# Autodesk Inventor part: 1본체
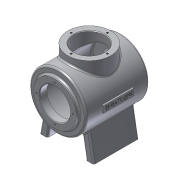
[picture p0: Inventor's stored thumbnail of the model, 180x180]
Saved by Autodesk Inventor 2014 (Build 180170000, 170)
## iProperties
Created: 2015-01
Part Number: 1본체
Material: 알루미늄 6061
Document SubType Name: Modeling
Designer: L-10
Density: 2.71 g/cm^3
Appearance: 알루미늄 - 평지
Mass: 953.119 g
Surface Area: 1057.99 cm^2
Volume: 351.704 cm^3
Author: L-10
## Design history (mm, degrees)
sketch "스케치1"
  geometry: C1 r 50 at (0, 0); 1 further point
  constraints: 1 centre point, 1 coincident
  dimensions: "d0" = 100 diameter of C1
extrude "돌출1" new body sketch "스케치1" distance "d1" = 112; taper "d2" = 0 deg
sketch "스케치2"
  geometry: C1 r 50 at (0, 0) reference; C2 r 38 at (0, 0)
  constraints: 1 centre point, 1 coincident
  dimensions: "d3" = 76 diameter of C2
extrude "돌출2" join sketch "스케치2" distance "d4" = 5; taper "d5" = 0 deg
node "작업 평면1"
node "작업 평면2"
sketch "스케치3"
  geometry: L1 (50, 112)-(-50, 112) reference; L2 (-50, 0)-(50, 0) reference; L3 (-50, 0)-(-50, 112) reference; L4 (50, 0)-(50, 112) reference; C1 r 38 at (0, 56); 1 further point
  constraints: 1 centre point
  dimensions: "d7" = 76 diameter of C1; "d8" = 112 distance of L3.start L3.end (derived); "d10" = 0 horizontal distance of point (0, 0) C1.centre; "d11" = 56 distance from line of L1 C1.centre (= 0.5 x d8)
extrude "돌출3" join sketch "스케치3" stored distance "d12" = 5; taper "d13" = 0 deg
sketch "스케치5"
  geometry: L1 (-39.336, 30.865)-(-48, 80); L2 (-48, 80)-(-34, 80); L3 (-34, 80)-(-27.282, 41.901); A1 r 50 centre (0, 0) between (-27.282, 41.901) and (-39.336, 30.865) reference; A2 r 50 centre (0, 0) between (-27.282, 41.901) and (-39.336, 30.865); 1 further point
  constraints: 6 end point, 4 point on circle, 1 centre point, 1 concentric, 1 horizontal, 1 parallel
  dimensions: "d14" = 100 deg angle of L2 L1; "d15" = 80 deg angle of L2 L3 (derived); "d16" = 14 distance of L1.end L2.end; "d17" = 80 distance from line of L2 point (0, 0); "d18" = 48 horizontal distance of point (0, 0) L1.end
extrude "돌출4" join sketch "스케치5" stored distance "d19" = 80; taper "d20" = 0 deg
node "작업 평면3"
sketch "스케치6"
  geometry: L1 (29, 6)-(83, 6); L2 (83, 6)-(83, -6); L3 (83, -6)-(29, -6); L4 (29, -6)-(29, 6); L5 (0, 50)-(112, 50) reference; L6 (0, 50)-(0, -50) reference; L7 (112, -50)-(112, 50) reference; L8 (0, -50)-(112, -50) reference; 1 further point
  constraints: 8 end point, 2 parallel, 1 horizontal, 1 perpendicular
  dimensions: "d22" = 54 distance of L1.start L1.end; "d23" = 12 distance of L3.end L1.start; "d24" = 6 distance from line of point (0, 0) L1 (= 0.5 x d23); "d25" = 112 distance of L5.start L5.end (derived); "d26" = 29 distance between parallel lines of L6 L4 (= -0.5 x d22 + 0.5 x d25)
extrude "돌출5" join sketch "스케치6" stored distance "d27" = 80; taper "d28" = 0 deg
sketch "스케치7"
  geometry: L1 (-6, 29)-(-6, 83) reference; L2 (6, 29)-(-6, 29) reference; 3 further points
  constraints: 1 other
  dimensions: "d29" = 54 distance of L1.start L1.end (derived); "d30" = 12 distance of L1.end point (6, 83) (derived); "d31" = 6 distance from line of L1 point (0, 56) (= 0.5 x d30); "d32" = 27 distance from line of L2 point (0, 56) (= 0.5 x d29)
feature "엠보싱1" sketch "스케치7" dims "d33" = 0.5, "d34" = 0
hole "구멍1" diameter "d37" = 54; stored, may be unused: countersink angle "d41" = 90 deg, drill point angle "d43" = 118 deg; dims "d35" = 10, "d36" = 10, "d38" = 6, "d39" = 4, "d40" = 2, "d42" = 8
node "작업 평면4"
sketch "스케치9"
  geometry: C1 r 45 at (0, 0); 1 further point
  constraints: 1 centre point, 1 coincident
  dimensions: "d48" = 90 diameter of C1
extrude "돌출7" cut sketch "스케치9" distance "d49" = 97; taper "d50" = 0 deg
hole "구멍2" diameter "d53" = 54; stored, may be unused: countersink angle "d57" = 90 deg, drill point angle "d59" = 118 deg; dims "d51" = 10, "d52" = 10, "d54" = 6, "d55" = 4, "d56" = 2, "d58" = 8
sketch "스케치10"
  geometry: C1 r 27 at (0, 0) reference; 2 further points
  dimensions: "d60" = 0 horizontal distance of point (0, 32) C1.centre; "d61" = 32 distance of C1.centre point (0, 32)
hole "구멍3" sketch "스케치10" at (0, 32) diameter "d62" = 3.242; stored, may be unused: countersink angle "d66" = 90 deg, drill point angle "d68" = 118 deg; dims "d63" = 8, "d64" = 4, "d65" = 2, "d67" = 10
sketch "스케치11"
  geometry: C1 r 27 at (0, 0) reference; 1 further point
  dimensions: "d72" = 0 horizontal distance of point (0, 32) C1.centre; "d73" = 32 distance of C1.centre point (0, 32)
hole "구멍4" sketch "스케치11" at (0, 32) diameter "d74" = 3.242; stored, may be unused: countersink angle "d78" = 90 deg, drill point angle "d80" = 118 deg; dims "d75" = 8, "d76" = 4, "d77" = 2, "d79" = 10
chamfer "모따기1" distance "d84" = 1; stored, may be unused: second distance "d85" = 2, angle "d86" = 45 deg
chamfer "모따기2" distance "d87" = 1; stored, may be unused: second distance "d88" = 2, angle "d89" = 45 deg
chamfer "모따기3" distance "d90" = 1; stored, may be unused: second distance "d91" = 2, angle "d92" = 45 deg
fillet "모깎기1" dims "d93" = 3
fillet "모깎기2" dims "d94" = 3
fillet "모깎기3" dims "d95" = 3
fillet "모깎기4" dims "d96" = 3
fillet "모깎기5" dims "d97" = 3
fillet "모깎기6" dims "d98" = 3
node "솔리드1"
mirror "대칭1"
mirror "대칭2"
pattern_circular "원형 패턴1" dims angle "d70" = 360 deg
pattern_circular "원형 패턴2" dims angle "d82" = 360 deg
mirror "대칭3"
node "투영된 루프1"
other parameters: "d6" = 62, "d21" = 52, "d47" = -8
